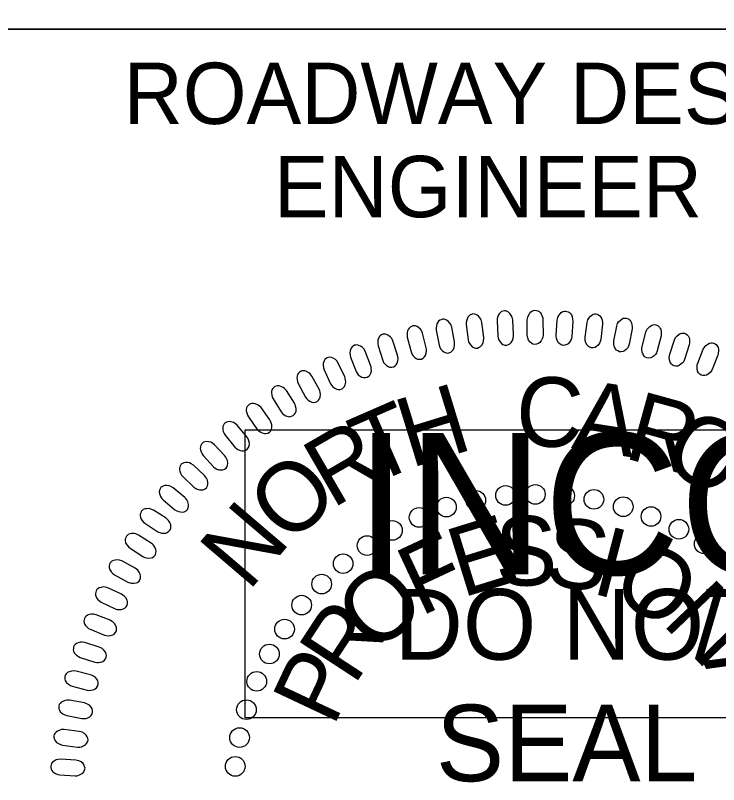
# Model space of a CAD drawing. Extents: x 505602 to 507286, y 483109 to 484209.
# Drawn here: x 507076.9 to 507134.2, y 484097.1 to 484159.8 of the extents above; entities that cross this region are included whole.
import ezdxf

# ---------------------------------------------------------------- set-up
doc = ezdxf.new("R2010")
doc.units = 0
for name, color, linetype in [('Sheet PE Seal Cell', 7, 'Continuous'), ('Sheet Profile CELL', 7, 'Continuous'), ('Sheet Sticker Incomplete CELL', 7, 'Continuous')]:
    doc.layers.add(name, color=color, linetype=linetype)

msp = doc.modelspace()

# ---------------------------------------------------------------- linework, layer by layer
at = {"layer": 'Sheet PE Seal Cell'}
for points in [[(507115.061, 484133.528), (507114.908, 484134.745), (507114.844, 484134.959), (507114.774, 484135.09), (507114.642, 484135.245), (507114.531, 484135.341), (507114.411, 484135.406), (507114.301, 484135.433), (507114.187, 484135.439), (507114.079, 484135.405), (507113.964, 484135.36), (507113.868, 484135.288), (507113.776, 484135.176), (507113.727, 484135.089), (507113.679, 484134.932), (507113.642, 484134.747), (507113.64, 484134.585), (507113.79, 484133.338), (507113.833, 484133.172), (507113.895, 484133.039), (507114.003, 484132.892), (507114.132, 484132.768), (507114.239, 484132.701), (507114.402, 484132.661), (507114.553, 484132.66), (507114.696, 484132.718), (507114.794, 484132.781), (507114.907, 484132.896), (507115.005, 484133.079), (507115.049, 484133.265), (507115.062, 484133.397)], [(507117.5, 484133.731), (507117.423, 484134.955), (507117.372, 484135.172), (507117.311, 484135.307), (507117.188, 484135.47), (507117.085, 484135.574), (507116.968, 484135.646), (507116.861, 484135.68), (507116.747, 484135.692), (507116.637, 484135.665), (507116.52, 484135.628), (507116.419, 484135.562), (507116.321, 484135.456), (507116.266, 484135.372), (507116.208, 484135.219), (507116.159, 484135.036), (507116.147, 484134.876), (507116.218, 484133.621), (507116.251, 484133.453), (507116.305, 484133.316), (507116.404, 484133.163), (507116.525, 484133.031), (507116.626, 484132.957), (507116.787, 484132.907), (507116.938, 484132.896), (507117.085, 484132.946), (507117.186, 484133.002), (507117.306, 484133.11), (507117.415, 484133.286), (507117.471, 484133.47), (507117.493, 484133.601)], [(507118.615, 484133.74), (507118.615, 484134.966), (507118.653, 484135.186), (507118.705, 484135.326), (507118.817, 484135.495), (507118.915, 484135.605), (507119.027, 484135.685), (507119.131, 484135.724), (507119.244, 484135.744), (507119.355, 484135.724), (507119.475, 484135.694), (507119.58, 484135.635), (507119.684, 484135.535), (507119.744, 484135.454), (507119.811, 484135.305), (507119.871, 484135.126), (507119.894, 484134.966), (507119.901, 484133.71), (507119.878, 484133.54), (507119.833, 484133.4), (507119.744, 484133.241), (507119.631, 484133.101), (507119.534, 484133.022), (507119.377, 484132.962), (507119.228, 484132.942), (507119.078, 484132.982), (507118.974, 484133.031), (507118.846, 484133.131), (507118.727, 484133.301), (507118.66, 484133.481), (507118.63, 484133.61)], [(507120.974, 484133.713), (507121.051, 484134.938), (507121.102, 484135.154), (507121.163, 484135.29), (507121.286, 484135.452), (507121.39, 484135.556), (507121.507, 484135.628), (507121.614, 484135.661), (507121.727, 484135.674), (507121.838, 484135.647), (507121.955, 484135.61), (507122.056, 484135.544), (507122.154, 484135.438), (507122.209, 484135.354), (507122.267, 484135.201), (507122.315, 484135.018), (507122.327, 484134.857), (507122.255, 484133.602), (507122.222, 484133.434), (507122.169, 484133.298), (507122.069, 484133.145), (507121.948, 484133.012), (507121.846, 484132.938), (507121.686, 484132.889), (507121.535, 484132.878), (507121.389, 484132.927), (507121.287, 484132.984), (507121.167, 484133.092), (507121.059, 484133.268), (507121.002, 484133.452), (507120.981, 484133.583)], [(507123.336, 484133.538), (507123.491, 484134.755), (507123.555, 484134.968), (507123.625, 484135.1), (507123.757, 484135.254), (507123.868, 484135.351), (507123.989, 484135.416), (507124.097, 484135.443), (507124.211, 484135.448), (507124.32, 484135.414), (507124.434, 484135.369), (507124.531, 484135.297), (507124.622, 484135.184), (507124.672, 484135.098), (507124.72, 484134.941), (507124.756, 484134.755), (507124.759, 484134.595), (507124.608, 484133.347), (507124.564, 484133.181), (507124.503, 484133.049), (507124.394, 484132.902), (507124.265, 484132.777), (507124.159, 484132.71), (507123.995, 484132.671), (507123.844, 484132.669), (507123.701, 484132.728), (507123.603, 484132.79), (507123.489, 484132.905), (507123.392, 484133.089), (507123.348, 484133.275), (507123.335, 484133.408)], [(507112.68, 484133.16), (507112.451, 484134.365), (507112.373, 484134.573), (507112.296, 484134.701), (507112.153, 484134.847), (507112.038, 484134.936), (507111.913, 484134.994), (507111.803, 484135.013), (507111.688, 484135.012), (507111.582, 484134.971), (507111.47, 484134.919), (507111.378, 484134.841), (507111.294, 484134.723), (507111.25, 484134.634), (507111.213, 484134.474), (507111.187, 484134.287), (507111.195, 484134.126), (507111.423, 484132.89), (507111.476, 484132.728), (507111.546, 484132.599), (507111.665, 484132.459), (507111.801, 484132.343), (507111.911, 484132.283), (507112.077, 484132.253), (507112.227, 484132.262), (507112.367, 484132.329), (507112.46, 484132.397), (507112.566, 484132.519), (507112.652, 484132.708), (507112.685, 484132.897), (507112.689, 484133.03)], [(507125.676, 484133.252), (507125.906, 484134.456), (507125.984, 484134.665), (507126.062, 484134.792), (507126.204, 484134.938), (507126.319, 484135.027), (507126.444, 484135.084), (507126.555, 484135.104), (507126.669, 484135.103), (507126.775, 484135.062), (507126.887, 484135.01), (507126.979, 484134.932), (507127.063, 484134.814), (507127.106, 484134.725), (507127.144, 484134.565), (507127.17, 484134.377), (507127.162, 484134.216), (507126.933, 484132.981), (507126.879, 484132.819), (507126.809, 484132.69), (507126.691, 484132.55), (507126.554, 484132.434), (507126.444, 484132.374), (507126.279, 484132.344), (507126.128, 484132.353), (507125.989, 484132.42), (507125.896, 484132.489), (507125.789, 484132.611), (507125.704, 484132.8), (507125.671, 484132.988), (507125.666, 484133.122)], [(507110.375, 484132.688), (507110.07, 484133.876), (507109.98, 484134.079), (507109.894, 484134.202), (507109.743, 484134.338), (507109.622, 484134.42), (507109.494, 484134.47), (507109.382, 484134.483), (507109.269, 484134.474), (507109.165, 484134.427), (507109.057, 484134.368), (507108.97, 484134.284), (507108.893, 484134.161), (507108.855, 484134.07), (507108.827, 484133.907), (507108.814, 484133.719), (507108.832, 484133.559), (507109.137, 484132.34), (507109.2, 484132.181), (507109.279, 484132.057), (507109.405, 484131.925), (507109.549, 484131.817), (507109.662, 484131.765), (507109.83, 484131.745), (507109.979, 484131.763), (507110.114, 484131.838), (507110.203, 484131.913), (507110.301, 484132.041), (507110.375, 484132.235), (507110.396, 484132.426), (507110.392, 484132.558)], [(507127.981, 484132.778), (507128.286, 484133.966), (507128.377, 484134.169), (507128.463, 484134.292), (507128.614, 484134.428), (507128.735, 484134.51), (507128.863, 484134.559), (507128.975, 484134.572), (507129.089, 484134.563), (507129.192, 484134.516), (507129.3, 484134.457), (507129.387, 484134.373), (507129.463, 484134.251), (507129.501, 484134.159), (507129.529, 484133.997), (507129.543, 484133.808), (507129.525, 484133.647), (507129.219, 484132.429), (507129.154, 484132.271), (507129.076, 484132.146), (507128.95, 484132.014), (507128.806, 484131.907), (507128.693, 484131.853), (507128.526, 484131.835), (507128.376, 484131.853), (507128.241, 484131.929), (507128.152, 484132.003), (507128.054, 484132.131), (507127.98, 484132.325), (507127.96, 484132.516), (507127.963, 484132.648)], [(507108.041, 484132.067), (507107.662, 484133.234), (507107.56, 484133.431), (507107.467, 484133.548), (507107.308, 484133.675), (507107.181, 484133.749), (507107.05, 484133.79), (507106.938, 484133.796), (507106.825, 484133.78), (507106.724, 484133.727), (507106.621, 484133.661), (507106.539, 484133.573), (507106.47, 484133.445), (507106.438, 484133.35), (507106.42, 484133.187), (507106.419, 484132.998), (507106.447, 484132.839), (507106.827, 484131.642), (507106.901, 484131.488), (507106.987, 484131.369), (507107.121, 484131.245), (507107.271, 484131.147), (507107.388, 484131.101), (507107.556, 484131.092), (507107.704, 484131.119), (507107.834, 484131.203), (507107.919, 484131.283), (507108.009, 484131.417), (507108.07, 484131.616), (507108.079, 484131.807), (507108.067, 484131.94)], [(507130.231, 484132.156), (507130.61, 484133.323), (507130.714, 484133.52), (507130.807, 484133.636), (507130.966, 484133.763), (507131.092, 484133.837), (507131.223, 484133.878), (507131.335, 484133.884), (507131.448, 484133.868), (507131.549, 484133.814), (507131.653, 484133.748), (507131.735, 484133.659), (507131.803, 484133.533), (507131.835, 484133.438), (507131.853, 484133.275), (507131.854, 484133.086), (507131.826, 484132.927), (507131.444, 484131.73), (507131.371, 484131.575), (507131.285, 484131.456), (507131.15, 484131.332), (507131, 484131.235), (507130.883, 484131.189), (507130.715, 484131.18), (507130.567, 484131.208), (507130.437, 484131.292), (507130.353, 484131.372), (507130.263, 484131.505), (507130.202, 484131.704), (507130.193, 484131.895), (507130.205, 484132.028)], [(507132.514, 484131.421), (507132.966, 484132.561), (507133.082, 484132.751), (507133.182, 484132.862), (507133.349, 484132.979), (507133.48, 484133.045), (507133.613, 484133.077), (507133.725, 484133.076), (507133.837, 484133.054), (507133.933, 484132.994), (507134.034, 484132.922), (507134.109, 484132.827), (507134.17, 484132.696), (507134.196, 484132.6), (507134.203, 484132.436), (507134.193, 484132.247), (507134.155, 484132.091), (507133.699, 484130.919), (507133.615, 484130.77), (507133.522, 484130.657), (507133.38, 484130.542), (507133.224, 484130.453), (507133.105, 484130.415), (507132.936, 484130.417), (507132.79, 484130.454), (507132.666, 484130.546), (507132.587, 484130.631), (507132.505, 484130.77), (507132.457, 484130.972), (507132.46, 484131.164), (507132.481, 484131.295)], [(507105.84, 484131.251), (507105.389, 484132.392), (507105.273, 484132.582), (507105.174, 484132.693), (507105.007, 484132.809), (507104.876, 484132.875), (507104.743, 484132.908), (507104.631, 484132.907), (507104.519, 484132.884), (507104.422, 484132.824), (507104.322, 484132.752), (507104.247, 484132.658), (507104.186, 484132.527), (507104.16, 484132.431), (507104.152, 484132.267), (507104.163, 484132.078), (507104.2, 484131.922), (507104.656, 484130.75), (507104.739, 484130.601), (507104.832, 484130.488), (507104.974, 484130.372), (507105.13, 484130.284), (507105.249, 484130.245), (507105.418, 484130.247), (507105.564, 484130.284), (507105.688, 484130.376), (507105.767, 484130.461), (507105.849, 484130.6), (507105.898, 484130.802), (507105.894, 484130.994), (507105.874, 484131.125)], [(507103.723, 484130.318), (507103.201, 484131.428), (507103.074, 484131.61), (507102.967, 484131.715), (507102.794, 484131.821), (507102.659, 484131.878), (507102.523, 484131.903), (507102.412, 484131.895), (507102.302, 484131.865), (507102.209, 484131.799), (507102.113, 484131.722), (507102.044, 484131.623), (507101.992, 484131.488), (507101.972, 484131.39), (507101.974, 484131.226), (507101.997, 484131.038), (507102.044, 484130.884), (507102.572, 484129.745), (507102.665, 484129.6), (507102.765, 484129.493), (507102.914, 484129.387), (507103.075, 484129.308), (507103.196, 484129.277), (507103.364, 484129.29), (507103.508, 484129.335), (507103.626, 484129.435), (507103.7, 484129.525), (507103.772, 484129.669), (507103.808, 484129.873), (507103.793, 484130.064), (507103.765, 484130.195)], [(507101.64, 484129.304), (507101.049, 484130.379), (507100.911, 484130.554), (507100.798, 484130.651), (507100.618, 484130.746), (507100.48, 484130.795), (507100.343, 484130.811), (507100.233, 484130.795), (507100.124, 484130.759), (507100.036, 484130.688), (507099.945, 484130.604), (507099.882, 484130.501), (507099.839, 484130.363), (507099.825, 484130.264), (507099.837, 484130.101), (507099.872, 484129.914), (507099.929, 484129.764), (507100.528, 484128.659), (507100.628, 484128.521), (507100.735, 484128.421), (507100.89, 484128.324), (507101.056, 484128.255), (507101.18, 484128.232), (507101.346, 484128.255), (507101.486, 484128.31), (507101.599, 484128.417), (507101.666, 484128.511), (507101.73, 484128.66), (507101.753, 484128.866), (507101.726, 484129.056), (507101.689, 484129.183)], [(507099.622, 484128.162), (507098.965, 484129.198), (507098.816, 484129.364), (507098.698, 484129.453), (507098.512, 484129.537), (507098.371, 484129.577), (507098.234, 484129.584), (507098.124, 484129.562), (507098.019, 484129.519), (507097.934, 484129.442), (507097.85, 484129.353), (507097.793, 484129.246), (507097.758, 484129.106), (507097.751, 484129.007), (507097.774, 484128.844), (507097.82, 484128.661), (507097.886, 484128.513), (507098.553, 484127.448), (507098.662, 484127.317), (507098.775, 484127.223), (507098.937, 484127.137), (507099.106, 484127.079), (507099.23, 484127.063), (507099.395, 484127.097), (507099.532, 484127.16), (507099.637, 484127.274), (507099.699, 484127.372), (507099.753, 484127.524), (507099.763, 484127.732), (507099.723, 484127.92), (507099.679, 484128.044)], [(507097.622, 484126.807), (507096.901, 484127.8), (507096.742, 484127.956), (507096.618, 484128.038), (507096.427, 484128.11), (507096.284, 484128.141), (507096.147, 484128.14), (507096.038, 484128.111), (507095.936, 484128.061), (507095.857, 484127.979), (507095.778, 484127.885), (507095.728, 484127.775), (507095.702, 484127.632), (507095.7, 484127.533), (507095.734, 484127.372), (507095.791, 484127.191), (507095.867, 484127.049), (507096.599, 484126.028), (507096.717, 484125.904), (507096.835, 484125.817), (507097.001, 484125.741), (507097.174, 484125.694), (507097.3, 484125.686), (507097.462, 484125.73), (507097.594, 484125.802), (507097.692, 484125.922), (507097.747, 484126.023), (507097.792, 484126.179), (507097.789, 484126.387), (507097.738, 484126.572), (507097.686, 484126.694)], [(507095.741, 484125.419), (507094.959, 484126.364), (507094.791, 484126.509), (507094.662, 484126.584), (507094.468, 484126.643), (507094.323, 484126.666), (507094.185, 484126.656), (507094.08, 484126.619), (507093.98, 484126.563), (507093.906, 484126.476), (507093.834, 484126.377), (507093.79, 484126.265), (507093.774, 484126.121), (507093.778, 484126.021), (507093.822, 484125.863), (507093.89, 484125.687), (507093.975, 484125.549), (507094.769, 484124.576), (507094.895, 484124.46), (507095.018, 484124.381), (507095.189, 484124.315), (507095.364, 484124.279), (507095.49, 484124.279), (507095.649, 484124.333), (507095.777, 484124.413), (507095.867, 484124.539), (507095.916, 484124.644), (507095.95, 484124.802), (507095.934, 484125.009), (507095.872, 484125.19), (507095.812, 484125.309)], [(507093.954, 484123.879), (507093.114, 484124.774), (507092.937, 484124.909), (507092.803, 484124.975), (507092.605, 484125.022), (507092.46, 484125.035), (507092.323, 484125.017), (507092.219, 484124.974), (507092.124, 484124.912), (507092.056, 484124.82), (507091.989, 484124.716), (507091.954, 484124.602), (507091.946, 484124.457), (507091.956, 484124.358), (507092.01, 484124.203), (507092.089, 484124.031), (507092.181, 484123.9), (507093.037, 484122.978), (507093.169, 484122.87), (507093.297, 484122.799), (507093.472, 484122.744), (507093.65, 484122.718), (507093.775, 484122.726), (507093.93, 484122.791), (507094.053, 484122.879), (507094.134, 484123.01), (507094.177, 484123.118), (507094.201, 484123.277), (507094.173, 484123.483), (507094.098, 484123.66), (507094.032, 484123.775)], [(507092.291, 484122.27), (507091.398, 484123.11), (507091.212, 484123.233), (507091.074, 484123.291), (507090.874, 484123.325), (507090.728, 484123.33), (507090.592, 484123.302), (507090.492, 484123.253), (507090.401, 484123.185), (507090.339, 484123.09), (507090.278, 484122.982), (507090.25, 484122.866), (507090.251, 484122.721), (507090.268, 484122.622), (507090.331, 484122.471), (507090.421, 484122.304), (507090.522, 484122.178), (507091.433, 484121.313), (507091.571, 484121.213), (507091.704, 484121.15), (507091.882, 484121.106), (507092.06, 484121.093), (507092.185, 484121.108), (507092.336, 484121.182), (507092.453, 484121.277), (507092.526, 484121.414), (507092.561, 484121.524), (507092.576, 484121.685), (507092.534, 484121.888), (507092.45, 484122.06), (507092.376, 484122.17)], [(507090.678, 484120.483), (507089.733, 484121.266), (507089.54, 484121.376), (507089.399, 484121.426), (507089.197, 484121.447), (507089.051, 484121.442), (507088.918, 484121.407), (507088.821, 484121.352), (507088.734, 484121.278), (507088.677, 484121.179), (507088.625, 484121.067), (507088.603, 484120.949), (507088.614, 484120.805), (507088.637, 484120.708), (507088.709, 484120.561), (507088.81, 484120.399), (507088.918, 484120.281), (507089.881, 484119.474), (507090.026, 484119.383), (507090.162, 484119.329), (507090.343, 484119.296), (507090.521, 484119.293), (507090.645, 484119.318), (507090.791, 484119.4), (507090.901, 484119.502), (507090.966, 484119.643), (507090.995, 484119.755), (507090.999, 484119.917), (507090.945, 484120.117), (507090.849, 484120.283), (507090.768, 484120.389)], [(507089.153, 484118.781), (507088.123, 484119.447), (507087.918, 484119.534), (507087.773, 484119.567), (507087.57, 484119.564), (507087.425, 484119.542), (507087.297, 484119.491), (507087.207, 484119.425), (507087.129, 484119.341), (507087.085, 484119.237), (507087.046, 484119.12), (507087.038, 484119), (507087.066, 484118.858), (507087.1, 484118.764), (507087.189, 484118.626), (507087.308, 484118.478), (507087.429, 484118.373), (507088.481, 484117.685), (507088.635, 484117.612), (507088.777, 484117.574), (507088.96, 484117.562), (507089.138, 484117.581), (507089.258, 484117.62), (507089.393, 484117.719), (507089.491, 484117.833), (507089.538, 484117.981), (507089.553, 484118.095), (507089.539, 484118.256), (507089.461, 484118.449), (507089.347, 484118.603), (507089.254, 484118.698)], [(507087.939, 484116.758), (507086.904, 484117.416), (507086.699, 484117.502), (507086.553, 484117.533), (507086.349, 484117.53), (507086.204, 484117.506), (507086.077, 484117.454), (507085.987, 484117.387), (507085.91, 484117.303), (507085.867, 484117.197), (507085.828, 484117.081), (507085.822, 484116.96), (507085.851, 484116.819), (507085.886, 484116.725), (507085.976, 484116.588), (507086.095, 484116.441), (507086.218, 484116.337), (507087.275, 484115.657), (507087.43, 484115.585), (507087.572, 484115.548), (507087.755, 484115.538), (507087.933, 484115.558), (507088.052, 484115.597), (507088.187, 484115.698), (507088.284, 484115.814), (507088.33, 484115.961), (507088.344, 484116.076), (507088.328, 484116.237), (507088.25, 484116.428), (507088.134, 484116.581), (507088.04, 484116.677)], [(507086.636, 484114.709), (507085.561, 484115.301), (507085.351, 484115.373), (507085.203, 484115.395), (507085, 484115.379), (507084.857, 484115.346), (507084.733, 484115.287), (507084.648, 484115.214), (507084.576, 484115.126), (507084.54, 484115.018), (507084.509, 484114.899), (507084.51, 484114.778), (507084.548, 484114.638), (507084.589, 484114.548), (507084.687, 484114.416), (507084.816, 484114.277), (507084.945, 484114.18), (507086.042, 484113.569), (507086.201, 484113.506), (507086.345, 484113.479), (507086.528, 484113.48), (507086.705, 484113.511), (507086.822, 484113.558), (507086.95, 484113.666), (507087.039, 484113.788), (507087.076, 484113.938), (507087.083, 484114.053), (507087.057, 484114.213), (507086.966, 484114.399), (507086.841, 484114.545), (507086.742, 484114.634)], [(507085.527, 484112.585), (507084.417, 484113.108), (507084.203, 484113.168), (507084.054, 484113.18), (507083.853, 484113.151), (507083.712, 484113.11), (507083.592, 484113.042), (507083.511, 484112.964), (507083.446, 484112.871), (507083.416, 484112.762), (507083.392, 484112.64), (507083.401, 484112.521), (507083.447, 484112.384), (507083.494, 484112.295), (507083.601, 484112.171), (507083.738, 484112.04), (507083.872, 484111.951), (507085.007, 484111.409), (507085.169, 484111.358), (507085.314, 484111.339), (507085.497, 484111.352), (507085.671, 484111.394), (507085.784, 484111.448), (507085.906, 484111.564), (507085.988, 484111.691), (507086.015, 484111.843), (507086.014, 484111.959), (507085.978, 484112.117), (507085.876, 484112.297), (507085.742, 484112.434), (507085.637, 484112.517)], [(507084.587, 484110.467), (507083.447, 484110.918), (507083.229, 484110.964), (507083.08, 484110.968), (507082.881, 484110.926), (507082.743, 484110.876), (507082.628, 484110.801), (507082.553, 484110.718), (507082.492, 484110.621), (507082.47, 484110.51), (507082.454, 484110.387), (507082.47, 484110.268), (507082.525, 484110.134), (507082.577, 484110.049), (507082.691, 484109.931), (507082.836, 484109.81), (507082.976, 484109.73), (507084.141, 484109.26), (507084.307, 484109.219), (507084.454, 484109.209), (507084.635, 484109.233), (507084.806, 484109.286), (507084.916, 484109.347), (507085.03, 484109.471), (507085.103, 484109.602), (507085.121, 484109.756), (507085.113, 484109.872), (507085.068, 484110.027), (507084.954, 484110.2), (507084.812, 484110.329), (507084.702, 484110.405)], [(507083.712, 484108.277), (507082.545, 484108.656), (507082.325, 484108.689), (507082.176, 484108.683), (507081.98, 484108.629), (507081.845, 484108.57), (507081.735, 484108.488), (507081.665, 484108.401), (507081.611, 484108.3), (507081.596, 484108.187), (507081.587, 484108.064), (507081.611, 484107.947), (507081.674, 484107.816), (507081.732, 484107.734), (507081.853, 484107.624), (507082.005, 484107.512), (507082.15, 484107.441), (507083.342, 484107.045), (507083.51, 484107.014), (507083.657, 484107.014), (507083.837, 484107.05), (507084.004, 484107.113), (507084.111, 484107.181), (507084.216, 484107.311), (507084.281, 484107.447), (507084.289, 484107.602), (507084.274, 484107.717), (507084.219, 484107.869), (507084.094, 484108.035), (507083.944, 484108.154), (507083.83, 484108.223)], [(507083.007, 484106.022), (507081.819, 484106.327), (507081.598, 484106.345), (507081.449, 484106.33), (507081.257, 484106.263), (507081.126, 484106.197), (507081.021, 484106.108), (507080.957, 484106.016), (507080.909, 484105.913), (507080.9, 484105.8), (507080.9, 484105.676), (507080.931, 484105.559), (507081.002, 484105.434), (507081.064, 484105.356), (507081.193, 484105.253), (507081.352, 484105.151), (507081.501, 484105.089), (507082.716, 484104.769), (507082.886, 484104.749), (507083.032, 484104.757), (507083.209, 484104.805), (507083.372, 484104.878), (507083.474, 484104.952), (507083.571, 484105.09), (507083.627, 484105.23), (507083.626, 484105.384), (507083.603, 484105.498), (507083.539, 484105.646), (507083.404, 484105.804), (507083.247, 484105.914), (507083.128, 484105.975)], [(507082.496, 484103.726), (507081.291, 484103.956), (507081.069, 484103.961), (507080.921, 484103.936), (507080.734, 484103.857), (507080.608, 484103.783), (507080.508, 484103.687), (507080.45, 484103.592), (507080.409, 484103.486), (507080.408, 484103.372), (507080.415, 484103.249), (507080.453, 484103.135), (507080.532, 484103.013), (507080.599, 484102.94), (507080.733, 484102.845), (507080.899, 484102.753), (507081.051, 484102.701), (507082.284, 484102.457), (507082.455, 484102.448), (507082.601, 484102.466), (507082.774, 484102.524), (507082.932, 484102.608), (507083.029, 484102.688), (507083.117, 484102.831), (507083.165, 484102.975), (507083.154, 484103.129), (507083.124, 484103.241), (507083.05, 484103.385), (507082.906, 484103.534), (507082.742, 484103.634), (507082.62, 484103.687)], [(507082.076, 484101.412), (507080.859, 484101.566), (507080.636, 484101.556), (507080.491, 484101.522), (507080.309, 484101.432), (507080.187, 484101.35), (507080.094, 484101.248), (507080.042, 484101.15), (507080.008, 484101.041), (507080.014, 484100.927), (507080.028, 484100.804), (507080.074, 484100.693), (507080.161, 484100.577), (507080.232, 484100.508), (507080.372, 484100.422), (507080.542, 484100.34), (507080.698, 484100.298), (507081.944, 484100.132), (507082.115, 484100.134), (507082.259, 484100.161), (507082.428, 484100.229), (507082.581, 484100.323), (507082.672, 484100.41), (507082.752, 484100.558), (507082.79, 484100.704), (507082.769, 484100.857), (507082.733, 484100.967), (507082.65, 484101.106), (507082.497, 484101.245), (507082.327, 484101.335), (507082.202, 484101.381)], [(507081.789, 484099.068), (507080.565, 484099.145), (507080.343, 484099.122), (507080.2, 484099.078), (507080.024, 484098.977), (507079.908, 484098.887), (507079.822, 484098.78), (507079.776, 484098.678), (507079.749, 484098.568), (507079.762, 484098.455), (507079.784, 484098.333), (507079.837, 484098.225), (507079.93, 484098.115), (507080.006, 484098.05), (507080.151, 484097.973), (507080.326, 484097.902), (507080.484, 484097.869), (507081.738, 484097.783), (507081.908, 484097.794), (507082.05, 484097.83), (507082.215, 484097.91), (507082.362, 484098.013), (507082.448, 484098.105), (507082.517, 484098.258), (507082.546, 484098.406), (507082.516, 484098.557), (507082.473, 484098.665), (507082.382, 484098.798), (507082.22, 484098.928), (507082.045, 484099.007), (507081.917, 484099.044)]]:
    msp.add_lwpolyline(points, close=True, dxfattribs=at)
for centre in [(507114.414, 484120.247), (507116.843, 484120.644), (507119.272, 484120.723), (507121.661, 484120.603), (507124.049, 484120.323), (507112.025, 484119.69), (507126.438, 484119.725), (507109.796, 484118.854), (507128.707, 484118.927), (507107.621, 484117.793), (507130.976, 484117.891), (507105.55, 484116.559), (507133.046, 484116.695), (507103.599, 484115.085), (507101.847, 484113.413), (507100.214, 484111.7), (507098.82, 484109.749), (507097.585, 484107.717), (507096.549, 484105.487), (507095.712, 484103.177), (507095.154, 484100.906), (507094.795, 484098.556)]:
    msp.add_circle(centre, 0.801, dxfattribs=at)
at = {"layer": 'Sheet Profile CELL'}
for points in [[(507069.03, 484183.712), (507269.08, 484183.712), (507269.08, 484158.662), (507069.03, 484158.662)], [(507069.03, 484158.662), (507169.08, 484158.662), (507169.08, 484046.162), (507069.03, 484046.162)]]:
    msp.add_lwpolyline(points, close=True, dxfattribs=at)
at = {"layer": 'Sheet Sticker Incomplete CELL'}
msp.add_lwpolyline([(507095.597, 484102.505), (507095.597, 484126.005), (507242.597, 484126.005), (507242.597, 484102.505)], close=True, dxfattribs=at)

# ---------------------------------------------------------------- texts
at = {"layer": 'Sheet PE Seal Cell'}
for s, height, rotation, p in [('C', 5.669, 357.58768, (507117.59, 484124.734)), ('A', 5.669, 351.09832, (507122.165, 484124.526)), ('H', 5.669, 17.05575, (507109.084, 484122.851)), ('R', 5.669, 344.60896, (507126.371, 484123.732)), ('T', 5.669, 23.5451, (507105.906, 484121.441)), ('O', 5.669, 331.63025, (507129.326, 484123.078)), ('R', 5.669, 30.03446, (507102.685, 484119.522)), ('O', 5.669, 43.01317, (507099.209, 484116.494)), ('N', 5.669, 49.50253, (507095.863, 484112.739)), ('E', 5.669, 17.16862, (507113.281, 484112.282)), ('S', 5.669, 1.28903, (507116.048, 484113.241)), ('S', 5.669, 353.34923, (507119.909, 484113.343)), ('I', 5.669, 345.40944, (507123.709, 484112.711)), ('F', 5.669, 25.10842, (507109.891, 484110.743)), ('O', 5.669, 329.52984, (507125.213, 484112.539)), ('O', 5.669, 40.98802, (507106.194, 484107.605)), ('N', 5.669, 313.65025, (507129.525, 484110.235)), ('R', 5.669, 56.86761, (507104.48, 484105.058)), ('P', 5.669, 64.80741, (507102.793, 484101.696)), ('A', 5.669, 297.77065, (507132.862, 484107.154)), ('SEAL', 6.2363, 359.98136, (507111.164, 484097.347))]:
    msp.add_text(s, height=height, rotation=rotation, dxfattribs=at).set_placement(p)
at = {"layer": 'Sheet Profile CELL'}
for s, p in [('ROADWAY DESIGN', (507085.692, 484150.924)), ('ENGINEER', (507097.942, 484143.324))]:
    msp.add_text(s, height=5.0001, dxfattribs=at).set_placement(p)
at = {"layer": 'Sheet Sticker Incomplete CELL'}
for s, height, p in [('INCOMPLETE PLANS', 11.52, (507104.547, 484114.205)), ('DO NOT USE FOR R/W ACQUISITION', 5.76, (507107.797, 484107.255))]:
    msp.add_text(s, height=height, dxfattribs=at).set_placement(p)

doc.saveas('drawing.dxf')
